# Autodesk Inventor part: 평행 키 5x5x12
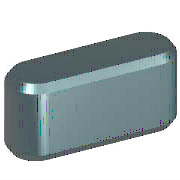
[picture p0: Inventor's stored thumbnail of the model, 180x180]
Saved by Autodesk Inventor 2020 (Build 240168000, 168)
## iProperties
IsCustomPart: 1
Created: 2012-02
Part Number: 평행 키 5x5x12
Material: 강철, 연강
Description: 평행 키
Document SubType Name: Modeling
Standard: JIS B 1301
Designer: mdu-01
Standards Organization: JIS
Language: ko-KR
Size Designation: 5x5x12
Categories: <MemberInstance><Categories><Category DisplayName="샤프트 부품" InternalName="7f7aeb1f-a693-4053-b835-cee3144e0d98" Mnemonic="SHFT"><Category DisplayName="키" Interna
Density: 1 g/cm^3
Appearance: 강철
Author: mdu-01
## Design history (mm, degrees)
workplane "Work Plane1"
workplane "Work Plane2"
sketch "스케치1"
  geometry: L1 (2.5, 2.5)-(9.5, 2.5); L2 (9.5, -2.5)-(2.5, -2.5); L3 (0, 9.4)-(0, -7.4) reference; L4 (-5, 0)-(30, 0) reference; L5 (12, 0)-(12, 7); A1 r 2.5 centre (2.5, 0) between (2.5, 2.5) and (2.5, -2.5); A2 r 2.5 centre (9.5, 0) between (9.5, -2.5) and (9.5, 2.5)
  constraints: 6 end point, 5 point on circle, 4 tangent, 3 point on line, 2 centre point, 1 horizontal, 1 parallel, 1 perpendicular
  dimensions: "d0" = 2.5 radius of A1 (= 0.5 x PB); "d13" = 2.5 radius of A2 (= 0.5 x PB); "d14" = 12 distance between parallel lines of L5 L3 (= NLG)
extrude "본체1" new body sketch "스케치1" taper "d3" = 0 deg; stored distance "d4" = 10
workplane "Work Plane3"
body "Solid1"
chamfer "모따기1" distance "d8" = 0.4 (= PHH); stored, may be unused: second distance "d9" = 0.4 (= PHH), angle "d15" = 45 deg
other parameters: "d1" = -3 (= -PNT), "d2" = 2 (= PH - PNT), "NLG" = 12 [user parameter; used in 3 equation terms], "PB" = 5 [user parameter; used in 2 equation terms], "PNT" = 3 [user parameter; used in 2 equation terms], "PH" = 5 [user parameter; used in 1 equation term], "PHH" = 0.4 [user parameter; used in 2 equation terms], "d10" = 0, "d16" = 0, "d17" = 0, "d18" = 0, "WDMIN" = 12 [user parameter], "PLB2" = 12 (= NLG) [user parameter], "WDMAX" = 17 [user parameter], "PLB1" = 12 (= NLG) [user parameter], "RR" = 0.16 [user parameter], "PUEB" = 2.3 [user parameter]
